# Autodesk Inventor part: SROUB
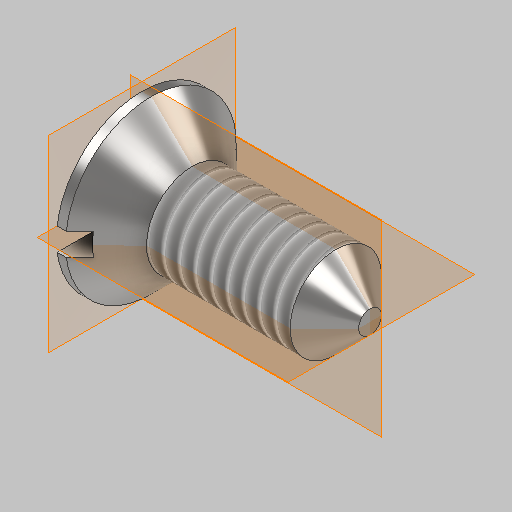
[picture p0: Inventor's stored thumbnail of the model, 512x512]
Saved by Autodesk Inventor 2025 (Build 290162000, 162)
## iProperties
Created: 2025-02
Part Number: SROUB
Material: Stainless Steel
Document SubType Name: Modeling
Designer: dansp
Mass: 1.16915 g
Surface Area: 2.06074 cm^2
Volume: 0.146144 cm^3
Density: 8 g/cm^3
Appearance: Semi-Polished
Author: dansp
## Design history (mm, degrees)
sketch "Sketch1"
  geometry: L1 (0, 4.5)-(0, -0.75) reference; L2 (-2, 0)-(12, 0) reference; L3 (0, 0)-(0, 3.75); L4 (0, 3.75)-(0.4, 3.75); L5 (0.4, 3.75)-(2.2, 2); L6 (2.2, 2)-(10, 2); L7 (10, 2)-(10, 0); L8 (10, 0)-(0, 0)
  constraints: 12 end point, 2 point on line, 1 collinear, 1 horizontal, 1 parallel, 1 perpendicular
  dimensions: "d0" = 10 distance between parallel lines of L7 L1; "d1" = 2.2 distance from line of L5.end L1; "d2" = 7.5 diameter of L4 L2; "d3" = 4 diameter of L6 L2; "d4" = 0.4 distance from line of L4.end L1
revolve "Revolution1" sketch "Sketch1" stored, may be unused: angle "d5" = 90 deg
sketch "Sketch2"
  geometry: L1 (-2, 0)-(12, 0) reference; L2 (0, 5.25)-(0, -5.25) reference; L3 (0, 0.5)-(1, 0.5); L4 (1, 0.5)-(1, -0.5); L5 (1, -0.5)-(0, -0.5); L6 (0, -0.5)-(0, 0.5); 2 further points
  constraints: 8 end point, 2 parallel, 1 horizontal, 1 perpendicular, 1 point on line, 1 other
  dimensions: "d6" = 1 distance between parallel lines of L3 L5; "d7" = 1 distance between parallel lines of L4 L2
extrude "Extrusion1" cut sketch "Sketch2" extent not by distance; stored distance "d8" = 0; taper "d9" = 0 deg
thread "Thread1" dims "d10" = 12.8, "d11" = 0
chamfer "Chamfer1" distance "d12" = 1.5; stored, may be unused: second distance "d13" = 2, angle "d14" = 45 deg
body "Solid1"
